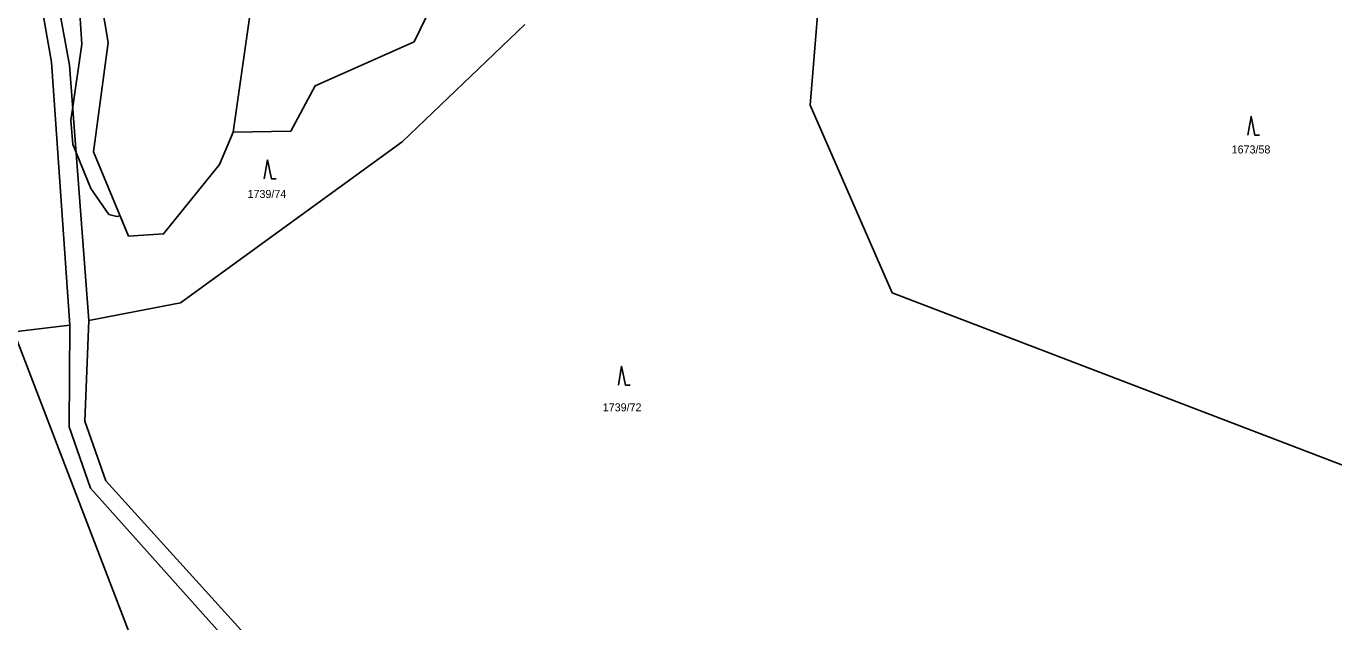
# Model space of a CAD drawing. Extents: x -445050 to -440454, y -1134563 to -1129741.
# Drawn here: x -444653.1 to -444375.4, y -1133247.2 to -1133120.7 of the extents above; entities that cross this region are included whole.
import ezdxf

# ---------------------------------------------------------------- set-up
doc = ezdxf.new("R2010")
doc.units = 0
for name, color, linetype in [('Vrstva 1', 7, 'Continuous'), ('Vrstva 18', 7, 'Continuous'), ('Vrstva 25', 7, 'Continuous'), ('Vrstva 52', 7, 'Continuous')]:
    doc.layers.add(name, color=color, linetype=linetype)

msp = doc.modelspace()

# ---------------------------------------------------------------- linework, layer by layer
at = {"layer": 'Vrstva 1'}
for points in [[(-444601.2, -1133087.24), (-444609.17, -1133143.22)], [(-444483.9, -1133103.64), (-444486.63, -1133137.52)], [(-444635.7, -1133124.21), (-444638.63, -1133107.02)], [(-444647.76, -1133128.37), (-444651.29, -1133108.15)], [(-444647.66, -1133108.49), (-444643.93, -1133128.99)], [(-444564.39, -1133110.9), (-444570.76, -1133124.08)], [(-444573.29, -1133145.3), (-444547.23, -1133120.38)], [(-444638.87, -1133147.45), (-444635.7, -1133124.21)], [(-444570.76, -1133124.08), (-444591.78, -1133133.41)], [(-444643.88, -1133184.2), (-444647.76, -1133128.37)], [(-444643.93, -1133128.99), (-444639.85, -1133183.21)], [(-444591.78, -1133133.41), (-444596.93, -1133143.03)], [(-444486.63, -1133137.52), (-444469.24, -1133177.38)], [(-444609.17, -1133143.22), (-444612.07, -1133150.1)], [(-444596.93, -1133143.03), (-444609.17, -1133143.22)], [(-444620.35, -1133179.49), (-444573.29, -1133145.3)], [(-444631.39, -1133165.31), (-444638.87, -1133147.45)], [(-444612.07, -1133150.1), (-444623.94, -1133164.86)], [(-444623.94, -1133164.86), (-444631.39, -1133165.31)], [(-444469.24, -1133177.38), (-444360.1, -1133219.12)], [(-444639.85, -1133183.21), (-444620.35, -1133179.49)], [(-444655.76, -1133185.65), (-444643.88, -1133184.2)], [(-444655.76, -1133185.65), (-444619.51, -1133280.15)], [(-444643.88, -1133184.2), (-444644, -1133205.77)], [(-444640.65, -1133204.6), (-444639.85, -1133183.21)], [(-444636.24, -1133217.24), (-444640.65, -1133204.6)], [(-444644, -1133205.77), (-444639.5, -1133218.83)], [(-444639.5, -1133218.83), (-444606.54, -1133255.64)], [(-444603.44, -1133253.41), (-444636.24, -1133217.24)]]:
    msp.add_lwpolyline(points, dxfattribs=at)
at = {"layer": 'Vrstva 25'}
for points in [[(-444393.69, -1133143.88), (-444392.99, -1133139.88), (-444392.19, -1133143.88), (-444391.19, -1133143.88)], [(-444602.57, -1133153.12), (-444601.87, -1133149.12), (-444601.07, -1133153.12), (-444600.07, -1133153.12)], [(-444527.38, -1133196.94), (-444526.68, -1133192.94), (-444525.88, -1133196.94), (-444524.88, -1133196.94)]]:
    msp.add_lwpolyline(points, dxfattribs=at)
at = {"layer": 'Vrstva 52'}
msp.add_lwpolyline([(-444564.39, -1133110.9), (-444570.76, -1133124.08), (-444591.78, -1133133.41), (-444596.93, -1133143.03), (-444609.17, -1133143.22), (-444612.07, -1133150.1), (-444623.94, -1133164.86), (-444631.39, -1133165.31), (-444633.18, -1133161.03), (-444633.88, -1133161.16), (-444635.58, -1133160.73), (-444639.41, -1133155.2), (-444642.53, -1133147.58), (-444643.25, -1133145.83), (-444643.67, -1133140.72), (-444643.26, -1133137.89), (-444641.33, -1133124.55), (-444641.97, -1133114.75)], dxfattribs=at)

# ---------------------------------------------------------------- texts
at = {"layer": 'Vrstva 18'}
for s, p in [('1673/58', (-444397.13, -1133147.76)), ('1739/74', (-444606.12, -1133157.21)), ('1739/72', (-444530.68, -1133202.51))]:
    msp.add_text(s, height=1.7, dxfattribs=at).set_placement(p)

doc.saveas('drawing.dxf')
